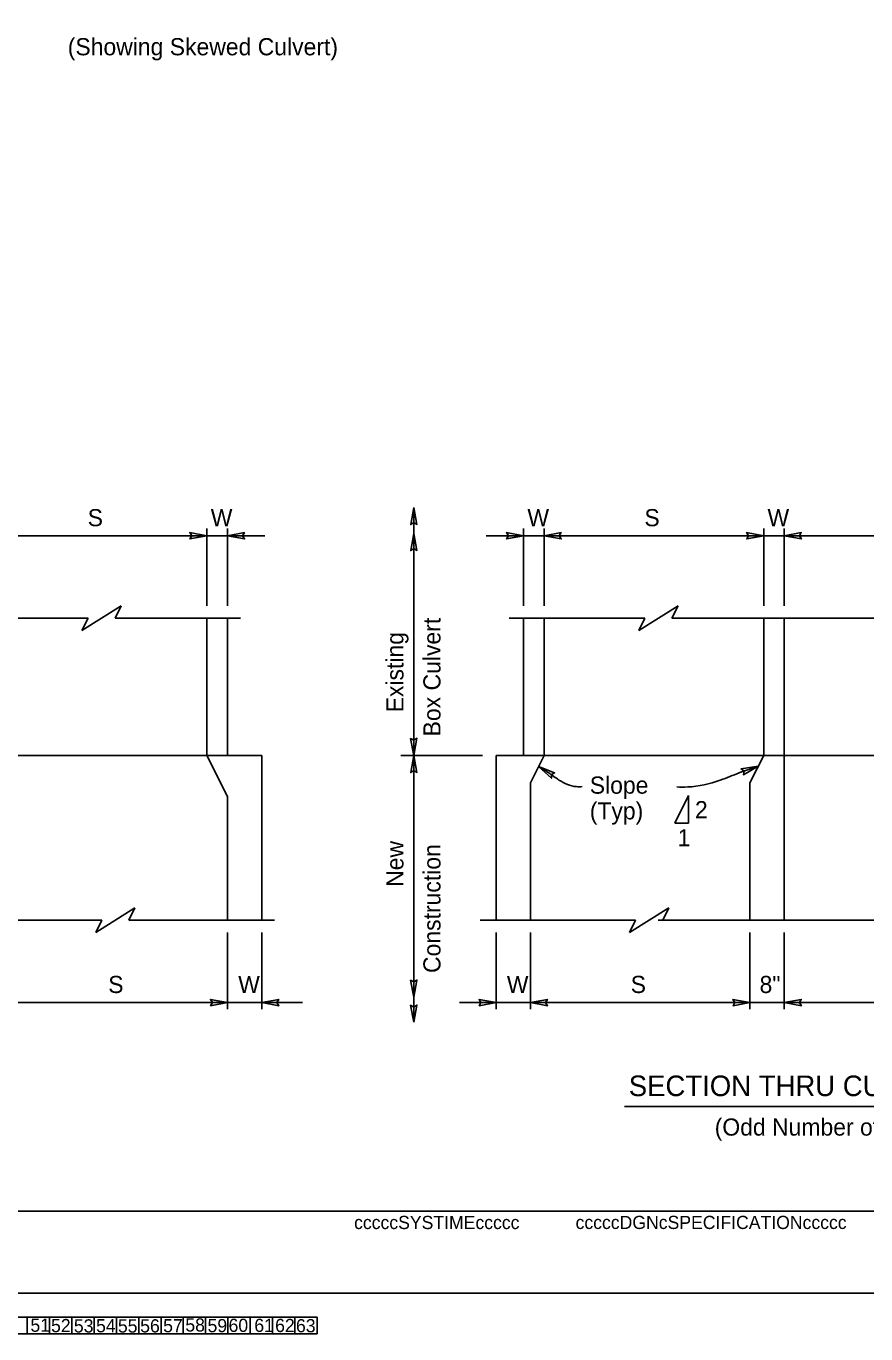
# Model space of a CAD drawing. Extents: x -0.08 to 2.83, y -0.03 to 1.92.
# Drawn here: x 0.951 to 1.588, y -0.031 to 0.961 of the extents above; entities that cross this region are included whole.
import ezdxf

# ---------------------------------------------------------------- set-up
doc = ezdxf.new("R2010")
doc.units = 0
for name, color, linetype in [('50', 7, 'Continuous'), ('51', 7, 'Continuous'), ('52', 7, 'Continuous'), ('53', 7, 'Continuous'), ('54', 7, 'Continuous'), ('55', 7, 'Continuous'), ('56', 7, 'Continuous'), ('57', 7, 'Continuous'), ('58', 7, 'Continuous'), ('59', 7, 'Continuous'), ('60', 7, 'Continuous'), ('61', 7, 'Continuous'), ('62', 7, 'Continuous'), ('63', 7, 'Continuous')]:
    doc.layers.add(name, color=color, linetype=linetype)

msp = doc.modelspace()

# ---------------------------------------------------------------- linework, layer by layer
at = {"layer": '50'}
for p, q in [((1.08806, 0.5123), (1.08806, 0.40813)), ((1.10368, 0.5123), (1.10368, 0.40813)), ((1.32846, 0.5123), (1.32846, 0.40813)), ((1.34408, 0.5123), (1.34408, 0.40813)), ((1.51075, 0.5123), (1.51075, 0.40813)), ((1.52638, 0.5123), (1.52638, 0.40813)), ((0.35889, 0.40813), (1.10368, 0.40813)), ((1.08806, 0.40813), (1.10368, 0.37688)), ((1.12972, 0.40813), (1.10368, 0.40813)), ((1.12972, 0.40813), (1.12972, 0.28313)), ((1.30763, 0.40813), (1.30763, 0.28313)), ((1.33193, 0.40813), (1.30763, 0.40813)), ((1.32846, 0.40813), (1.89096, 0.40813)), ((1.34408, 0.40813), (1.33367, 0.3873)), ((1.51075, 0.40813), (1.50033, 0.3873)), ((1.52638, 0.40813), (1.52638, 0.28313)), ((1.33367, 0.3873), (1.33367, 0.28313)), ((1.50033, 0.3873), (1.50033, 0.28313)), ((1.10368, 0.37688), (1.10368, 0.28313))]:
    msp.add_line(p, q, dxfattribs=at)
at = {"layer": '54'}
for points in [[(1.24513, 0.59632), (1.24275, 0.58333), (1.24513, 0.58484), (1.24753, 0.58348)], [(1.08806, 0.5748), (1.07506, 0.57717), (1.07657, 0.5748), (1.07521, 0.5724)], [(1.10368, 0.5748), (1.11667, 0.57242), (1.11516, 0.5748), (1.11652, 0.5772)], [(1.24513, 0.57656), (1.24275, 0.56357), (1.24513, 0.56508), (1.24753, 0.56372)], [(1.32846, 0.5748), (1.31547, 0.57717), (1.31698, 0.5748), (1.31562, 0.5724)], [(1.34408, 0.5748), (1.35708, 0.57242), (1.35557, 0.5748), (1.35693, 0.5772)], [(1.51075, 0.5748), (1.49776, 0.57717), (1.49927, 0.5748), (1.49791, 0.5724)], [(1.52638, 0.5748), (1.53937, 0.57242), (1.53786, 0.5748), (1.53922, 0.5772)], [(1.24513, 0.40813), (1.2475, 0.42112), (1.24513, 0.41962), (1.24273, 0.42097)], [(1.24513, 0.40813), (1.24275, 0.39514), (1.24513, 0.39665), (1.24753, 0.39529)], [(1.33986, 0.39969), (1.3496, 0.39076), (1.34958, 0.39358), (1.35201, 0.39488)], [(1.50668, 0.4), (1.49364, 0.39795), (1.49584, 0.3962), (1.49535, 0.39349)], [(1.24513, 0.22475), (1.2475, 0.23774), (1.24513, 0.23623), (1.24273, 0.23759)], [(1.10368, 0.22063), (1.09069, 0.22301), (1.0922, 0.22063), (1.09084, 0.21823)], [(1.12972, 0.22063), (1.14271, 0.21826), (1.14121, 0.22063), (1.14256, 0.22303)], [(1.24513, 0.20575), (1.2475, 0.21874), (1.24513, 0.21723), (1.24273, 0.21859)], [(1.30763, 0.22063), (1.29463, 0.22301), (1.29614, 0.22063), (1.29478, 0.21823)], [(1.33367, 0.22063), (1.34666, 0.21826), (1.34515, 0.22063), (1.34651, 0.22303)], [(1.50033, 0.22063), (1.48734, 0.22301), (1.48885, 0.22063), (1.48749, 0.21823)], [(1.52638, 0.22063), (1.53937, 0.21826), (1.53786, 0.22063), (1.53922, 0.22303)]]:
    msp.add_lwpolyline(points, close=True, dxfattribs=at)
at = {"layer": '55'}
for p, q in [((1.24513, 0.59632), (1.24513, 0.40813)), ((1.08806, 0.52155), (1.08806, 0.58036)), ((1.10368, 0.52155), (1.10368, 0.58036)), ((1.32846, 0.52155), (1.32846, 0.58036)), ((1.34408, 0.52155), (1.34408, 0.58036)), ((1.51075, 0.52155), (1.51075, 0.58036)), ((1.52638, 0.52155), (1.52638, 0.58036)), ((1.08806, 0.5748), (0.92139, 0.5748)), ((1.10368, 0.5748), (1.08806, 0.5748)), ((1.13215, 0.5748), (1.10368, 0.5748)), ((1.32846, 0.5748), (1.29999, 0.5748)), ((1.34408, 0.5748), (1.32846, 0.5748)), ((1.51075, 0.5748), (1.34408, 0.5748)), ((1.52638, 0.5748), (1.51075, 0.5748)), ((1.69304, 0.5748), (1.52638, 0.5748)), ((0.99319, 0.50305), (1.02302, 0.52155)), ((1.0184, 0.5123), (1.02302, 0.52155)), ((1.41588, 0.50305), (1.44572, 0.52155)), ((1.44109, 0.5123), (1.44572, 0.52155)), ((0.99781, 0.5123), (0.47153, 0.5123)), ((0.99319, 0.50305), (0.99781, 0.5123)), ((1.0184, 0.5123), (1.11354, 0.5123)), ((1.31759, 0.5123), (1.42051, 0.5123)), ((1.41588, 0.50305), (1.42051, 0.5123)), ((1.78509, 0.5123), (1.44109, 0.5123)), ((1.23519, 0.40813), (1.29734, 0.40813)), ((1.24513, 0.40813), (1.24513, 0.20575)), ((1.45365, 0.37762), (1.44323, 0.35679)), ((1.45365, 0.35679), (1.45365, 0.37762)), ((1.45365, 0.35679), (1.44323, 0.35679)), ((1.00361, 0.27389), (1.03344, 0.29238)), ((1.02882, 0.28313), (1.03344, 0.29238)), ((1.40894, 0.27389), (1.43877, 0.29238)), ((1.43415, 0.28313), (1.43877, 0.29238)), ((0.46111, 0.28313), (1.00823, 0.28313)), ((1.00361, 0.27389), (1.00823, 0.28313)), ((1.02882, 0.28313), (1.13924, 0.28313)), ((1.29561, 0.28313), (1.41356, 0.28313)), ((1.40894, 0.27389), (1.41356, 0.28313)), ((1.43068, 0.28313), (1.79204, 0.28313)), ((1.10368, 0.21563), (1.10368, 0.27389)), ((1.12972, 0.21563), (1.12972, 0.27389)), ((1.30763, 0.21563), (1.30763, 0.27389)), ((1.33367, 0.21563), (1.33367, 0.27389)), ((1.50033, 0.21563), (1.50033, 0.27389)), ((1.52638, 0.21563), (1.52638, 0.27389)), ((0.93701, 0.22063), (1.10368, 0.22063)), ((1.12972, 0.22063), (1.10368, 0.22063)), ((1.16051, 0.22063), (1.12972, 0.22063)), ((1.30763, 0.22063), (1.27989, 0.22063)), ((1.33367, 0.22063), (1.30763, 0.22063)), ((1.33367, 0.22063), (1.50033, 0.22063)), ((1.52638, 0.22063), (1.50033, 0.22063)), ((1.52638, 0.22063), (1.69304, 0.22063))]:
    msp.add_line(p, q, dxfattribs=at)
for points in [[(1.37303, 0.38445), (1.36861, 0.38445), (1.35535, 0.38948), (1.34762, 0.39481), (1.33986, 0.39969)], [(1.44484, 0.38419), (1.45308, 0.38419), (1.4778, 0.3894), (1.49221, 0.39493), (1.50668, 0.4)]]:
    msp.add_spline(points, degree=3, dxfattribs=at)
at = {"layer": '57'}
msp.add_line((1.40508, 0.14182), (1.8074, 0.14182), dxfattribs=at)
at = {"layer": '62'}
for p, q in [((0.10494, -0.01804), (1.17174, -0.01804)), ((0.95161, -0.01804), (0.95161, -0.03074)), ((0.96854, -0.01804), (0.96854, -0.03074)), ((0.98548, -0.01804), (0.98548, -0.03074)), ((1.00241, -0.01804), (1.00241, -0.03074)), ((1.01934, -0.01804), (1.01934, -0.03074)), ((1.03628, -0.01804), (1.03628, -0.03074)), ((1.05321, -0.01804), (1.05321, -0.03074)), ((1.07014, -0.01804), (1.07014, -0.03074)), ((1.08708, -0.01804), (1.08708, -0.03074)), ((1.10401, -0.01804), (1.10401, -0.03074)), ((1.12094, -0.01804), (1.12094, -0.03074)), ((1.13787, -0.01804), (1.13787, -0.03074)), ((1.15481, -0.01804), (1.15481, -0.03074)), ((1.17174, -0.01804), (1.17174, -0.03074)), ((0.10494, -0.03074), (1.17174, -0.03074))]:
    msp.add_line(p, q, dxfattribs=at)
at = {"layer": '63'}
msp.add_line((2.83333, 0), (0, 0), dxfattribs=at)
msp.add_lwpolyline([(0.16668, 0.06244), (0.16668, 1.77077), (2.72918, 1.77077), (2.72918, 0.10411), (2.56251, 0.10411), (2.56251, 0.14578), (2.07387, 0.14578), (2.07387, 0.06244)], close=True, dxfattribs=at)

# ---------------------------------------------------------------- texts
at = {"layer": '51'}
msp.add_text('51', height=0.01, rotation=360, dxfattribs=at).set_placement((0.95407, -0.02918))
at = {"layer": '52'}
msp.add_text('52', height=0.01, rotation=360, dxfattribs=at).set_placement((0.96972, -0.02946))
at = {"layer": '53'}
msp.add_text('53', height=0.01, rotation=360, dxfattribs=at).set_placement((0.98705, -0.0297))
at = {"layer": '54'}
msp.add_text('54', height=0.01, rotation=360, dxfattribs=at).set_placement((1.0039, -0.02958))
at = {"layer": '55'}
msp.add_text('55', height=0.01, rotation=360, dxfattribs=at).set_placement((1.02047, -0.02978))
at = {"layer": '56'}
msp.add_text('56', height=0.01, rotation=360, dxfattribs=at).set_placement((1.03739, -0.02967))
at = {"layer": '57'}
for s, height, p in [('(Showing Skewed Culvert)', 0.0130208, (0.98241, 0.93936)), ('S', 0.01302, (0.99752, 0.58203)), ('W', 0.01302, (1.09098, 0.58203)), ('W', 0.01302, (1.33138, 0.58203)), ('S', 0.01302, (1.42021, 0.58203)), ('W', 0.01302, (1.51367, 0.58203)), ('Slope', 0.013021, (1.37872, 0.3791)), ('(Typ)', 0.013021, (1.37872, 0.35957)), ('2', 0.01302, (1.45858, 0.36047)), ('1', 0.01302, (1.44543, 0.33916)), ('S', 0.01302, (1.01314, 0.22786)), ('W', 0.01302, (1.11181, 0.22786)), ('W', 0.01302, (1.31575, 0.22786)), ('S', 0.01302, (1.40979, 0.22786)), ('8"', 0.013021, (1.50764, 0.22786)), ('SECTION THRU CULVERT WALLS', 0.015625, (1.40832, 0.14963)), ('(Odd Number of Cells)', 0.0130208, (1.47357, 0.11967))]:
    msp.add_text(s, height=height, dxfattribs=at).set_placement(p)
for s, height, rotation, p in [('Box Culvert', 0.0130208, 90, (1.26539, 0.42258)), ('Existing', 0.013021, 90, (1.23727, 0.44082)), ('New', 0.013021, 90, (1.23727, 0.30841)), ('Construction', 0.0130208, 90, (1.26539, 0.24305)), ('57', 0.01, 360, (1.05482, -0.02955))]:
    msp.add_text(s, height=height, rotation=rotation, dxfattribs=at).set_placement(p)
at = {"layer": '58'}
msp.add_text('58', height=0.01, rotation=360, dxfattribs=at).set_placement((1.07167, -0.02898))
at = {"layer": '59'}
msp.add_text('59', height=0.01, rotation=360, dxfattribs=at).set_placement((1.08852, -0.0295))
at = {"layer": '60'}
msp.add_text('60', height=0.01, rotation=360, dxfattribs=at).set_placement((1.10448, -0.02929))
at = {"layer": '61'}
msp.add_text('61', height=0.01, rotation=360, dxfattribs=at).set_placement((1.12406, -0.02929))
at = {"layer": '62'}
for s, height, p in [('cccccSYSTIMEccccc', 0.0099989, (1.1998, 0.04875)), ('cccccDGNcSPECIFICATIONccccc', 0.0099989, (1.36796, 0.0488)), ('62', 0.01, (1.13984, -0.02938))]:
    msp.add_text(s, height=height, rotation=360, dxfattribs=at).set_placement(p)
at = {"layer": '63'}
msp.add_text('63', height=0.01, rotation=360, dxfattribs=at).set_placement((1.15568, -0.02958))

doc.saveas('drawing.dxf')
